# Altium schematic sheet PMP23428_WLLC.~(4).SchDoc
size 431 x 279 mm; Date: Not shown in title block; ApprovedBy: Not shown in title block; CheckedBy: Not shown in title block; Author: Not shown in title block; CompanyName: Not shown in title block; Engineer: Not shown in title block; Organization: Not shown in title block; Address1: Not shown in title block; Address2: Not shown in title block; Address3: Not shown in title block; Address4: Not shown in title block; DocumentNumber: 1; Revision: Use project parameter SCH_Rev; SheetNumber: 3; SheetTotal: 4; PageSetup: Record=PageOptions¦CenterHorizontal=True¦CenterVertical=True¦PrintScale=1.00¦XCorrection=1.00¦YCorrection=1.00¦PrintKind=0¦BorderSize=5000000¦LeftOffset=0¦BottomOffset=0¦Orientation=2¦PaperLength=1000¦PaperWidth=1000¦Scale=100¦PaperSource=15¦PrintQuality=600¦MediaType=1¦DitherType=10¦PaperKind=Letter¦PrintScaleMode=1
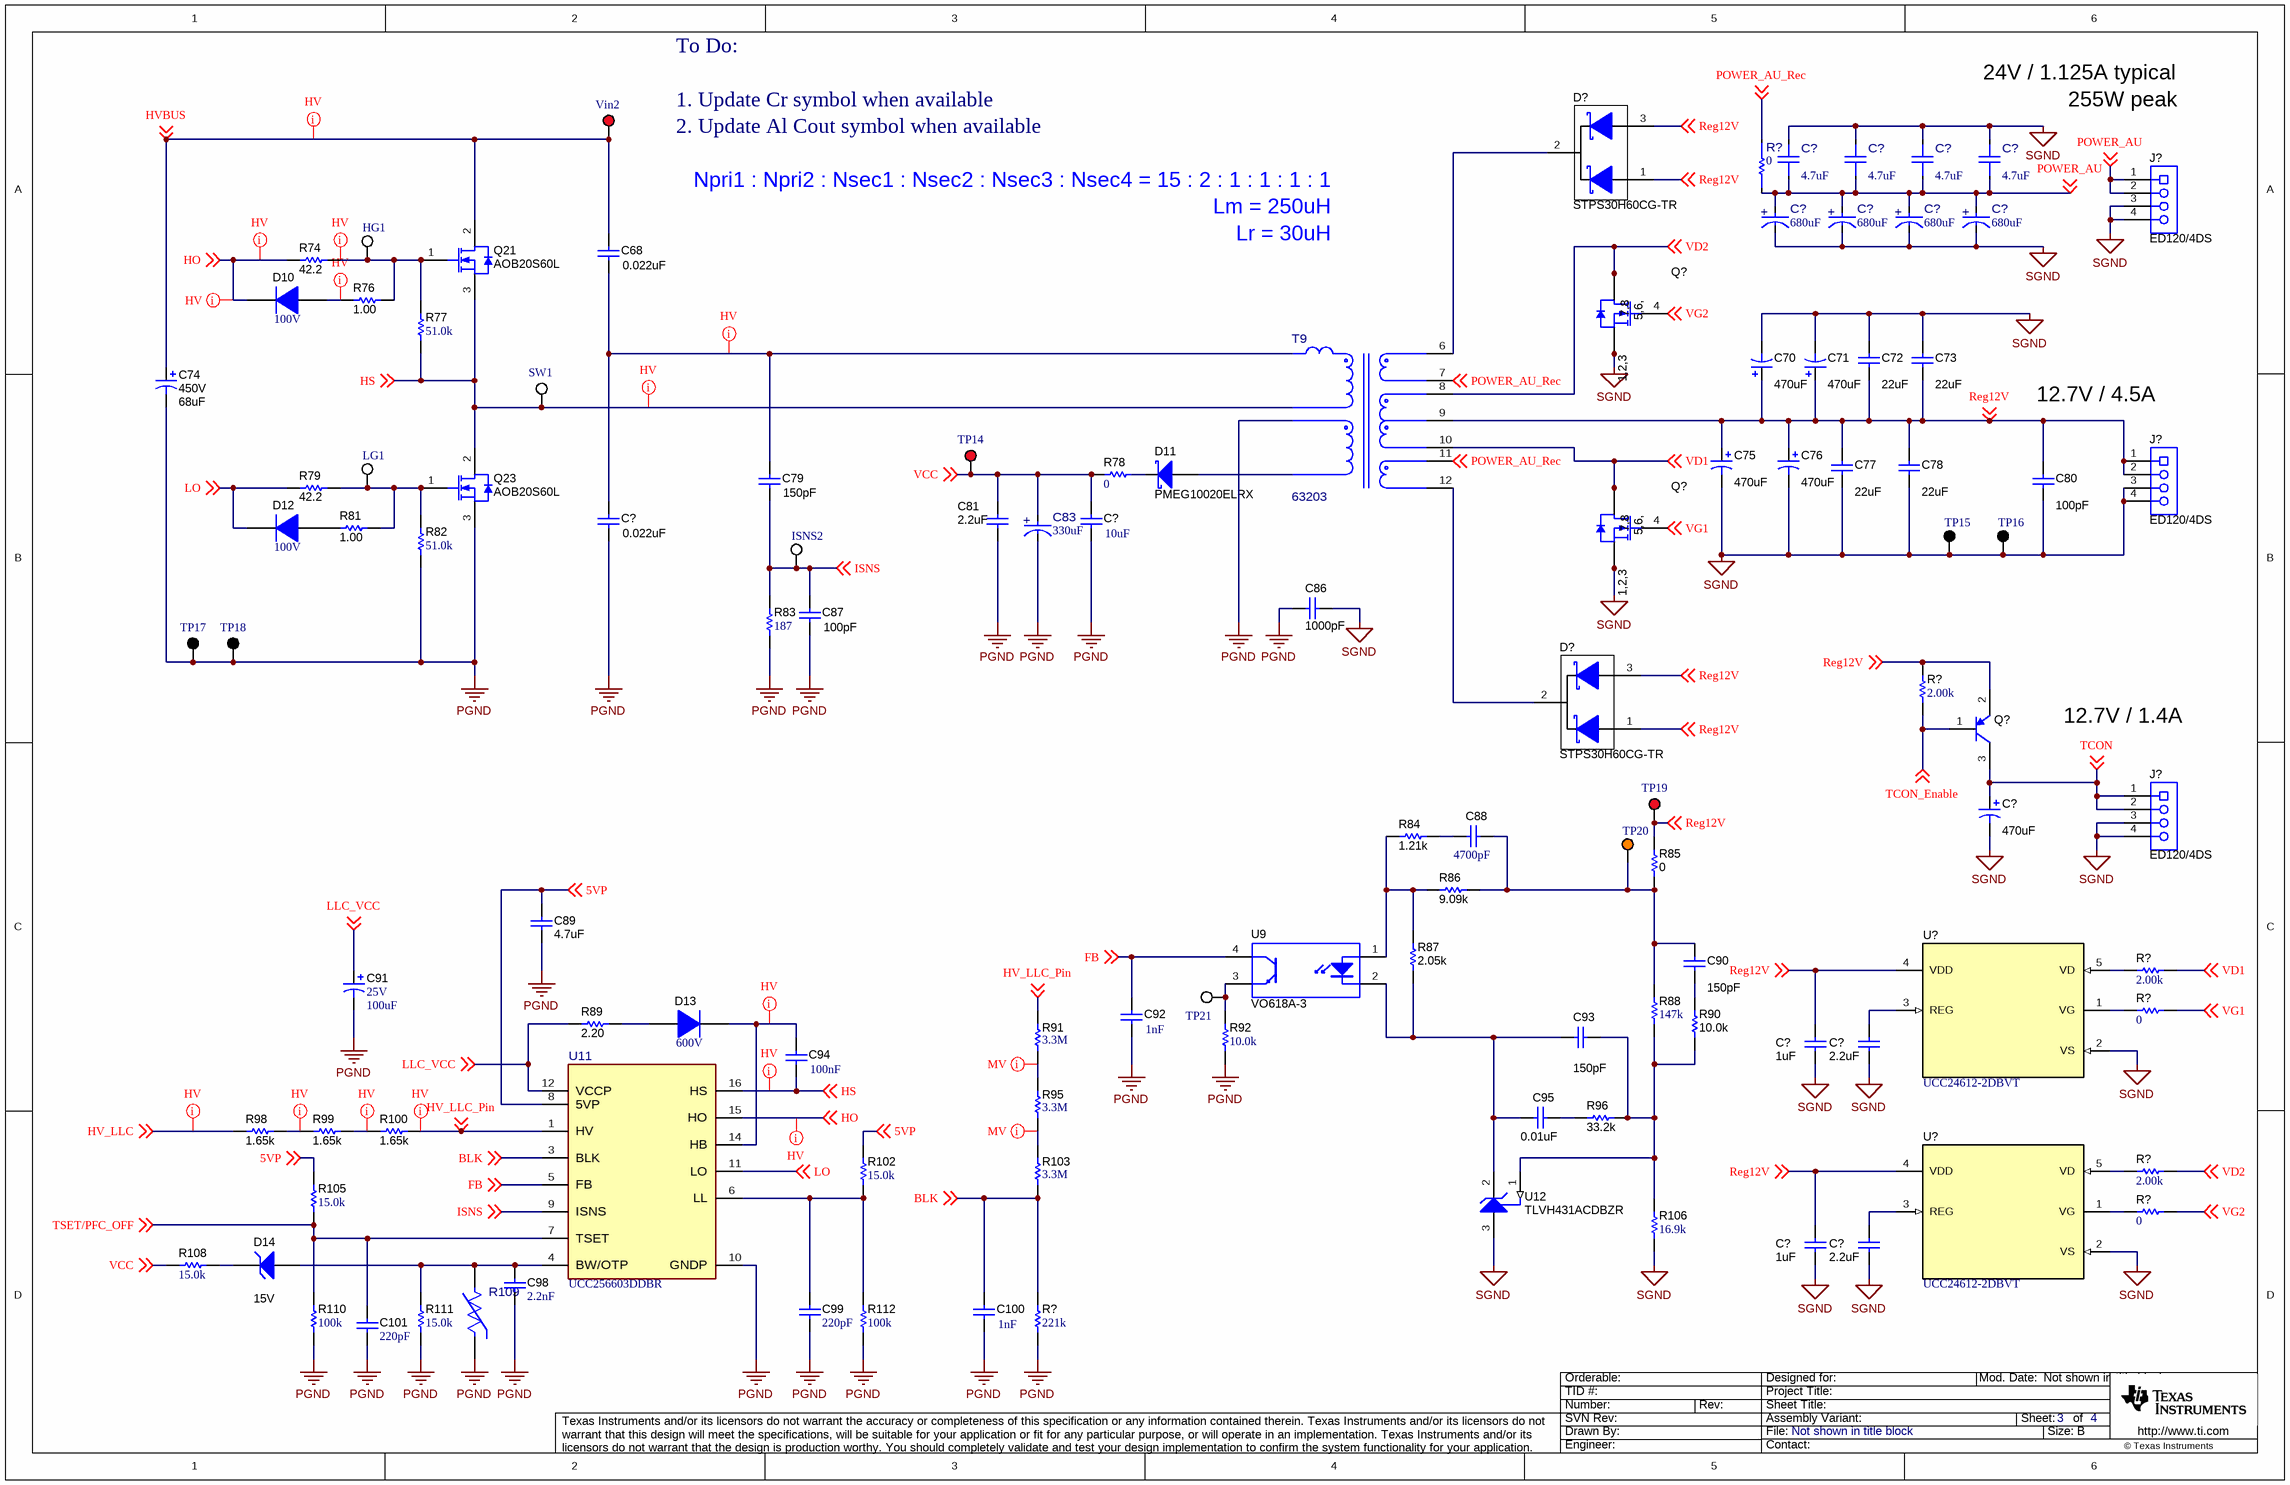
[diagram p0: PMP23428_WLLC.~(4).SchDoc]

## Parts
(Parts that share a designator on the sheet are numbered #1, #2 ... from top to bottom, then left to right.)
C68  ValueDisplayed: 0.022uF  [B32652_1800x700x1250]  (hidden comment: B32652A7153J000)
C70  ValueDisplayed: 470uF  [HW_1000x1600]  (hidden comment: UHW1V471MPD)
C71  ValueDisplayed: 470uF  [HW_1000x1600]  (hidden comment: UHW1V471MPD)
C72  ValueDisplayed: 22uF  [1206_190L]  (hidden comment: C3216X5R1E226M160AB)
C73  ValueDisplayed: 22uF  [1206_190L]  (hidden comment: C3216X5R1E226M160AB)
C74  VDC_V: 450V  ValueDisplayed: 68uF  [KXG_1800x3150]  (hidden comment: EKXG451ELL680MMN3S)
C75  ValueDisplayed: 470uF  [HW_1000x1600]  (hidden comment: UHW1V471MPD)
C76  ValueDisplayed: 470uF  [HW_1000x1600]  (hidden comment: UHW1V471MPD)
C77  ValueDisplayed: 22uF  [1206_190L]  (hidden comment: C3216X5R1E226M160AB)
C78  ValueDisplayed: 22uF  [1206_190L]  (hidden comment: C3216X5R1E226M160AB)
C79  ValueDisplayed: 150pF  [1206L]  (hidden comment: GRM31A5C2J151JW01D)
C80  ValueDisplayed: 100pF  [0603L]  (hidden comment: 06035A101FAT2A)
C81  ValueDisplayed: 2.2uF  [0805L]  (hidden comment: C2012X7R1V225K085AC)
C83  ValueDisplayed: 330uF  [FP-35ZL330MEFC10X16_RADIAL-MFG]  (hidden comment: 35ZL330MEFC10X16)
C86  ValueDisplayed: 1000pF  [CD45_700x600x1100]  (hidden comment: CD45-E2GA102M-NKA)
C87  ValueDisplayed: 100pF  [1206L]  (hidden comment: 12061A101JAT2A)
C88  ValueDisplayed: 4700pF  [0603L]  (hidden comment: C0603C472J1GAC7867)
C89  ValueDisplayed: 4.7uF  [1206L]  (hidden comment: C3216X7R1E475K085AB)
C90  ValueDisplayed: 150pF  [0402L]  (hidden comment: 885012005062)
C91  VDC_V: 25V  ValueDisplayed: 100uF  [SM_RADIAL_E]  (hidden comment: EEE-FK1E101P)
C92  Cap_F: 1nF  [1206L]  (hidden comment: 12061A102JAT2A)
C93  ValueDisplayed: 150pF  [0402L]  (hidden comment: 885012005062)
C94  Cap_F: 100nF  [1206_180L]  (hidden comment: GRM31C5C1E104JA01L)
C95  ValueDisplayed: 0.01uF  [0603L]  (hidden comment: 06031C103JAT2A)
C98  Cap_F: 2.2nF  [0603]  (hidden comment: C0603X222K5RACTU)
C99  Cap_F: 220pF  [0603]  (hidden comment: C0603X221K5RACTU)
C100  Cap_F: 1nF  [0402L]  (hidden comment: 04025C102JAT2A)
C101  Cap_F: 220pF  [0603]  (hidden comment: C0603X221K5RACTU)
C?#1  ValueDisplayed: 4.7uF  [FP-885012208094_1206-MFG]  (hidden comment: 885012208094)
C?#2  ValueDisplayed: 4.7uF  [FP-885012208094_1206-MFG]  (hidden comment: 885012208094)
C?#3  ValueDisplayed: 4.7uF  [FP-885012208094_1206-MFG]  (hidden comment: 885012208094)
C?#4  ValueDisplayed: 4.7uF  [FP-885012208094_1206-MFG]  (hidden comment: 885012208094)
C?#5  ValueDisplayed: 680uF  [FP-EKZM350ELL681MJ25S_RADIAL-MFG]  (hidden comment: EKZM350ELL681MJ25S)
C?#6  ValueDisplayed: 680uF  [FP-EKZM350ELL681MJ25S_RADIAL-MFG]  (hidden comment: EKZM350ELL681MJ25S)
C?#7  ValueDisplayed: 680uF  [FP-EKZM350ELL681MJ25S_RADIAL-MFG]  (hidden comment: EKZM350ELL681MJ25S)
C?#8  ValueDisplayed: 680uF  [FP-EKZM350ELL681MJ25S_RADIAL-MFG]  (hidden comment: EKZM350ELL681MJ25S)
C?#9  ValueDisplayed: 0.022uF  [B32652_1800x700x1250]  (hidden comment: B32652A7153J000)
C?#10  ValueDisplayed: 10uF  [1210_270]  (hidden comment: GRM32ER6YA106KA12L)
C?#11  ValueDisplayed: 470uF  [HW_1000x1600]  (hidden comment: UHW1V471MPD)
C?#12  ValueDisplayed: 1uF  [0603L]  (hidden comment: GRM188R71C105KE15D)
C?#13  ValueDisplayed: 2.2uF  [0805L]  (hidden comment: C2012X7R1V225K085AC)
C?#14  ValueDisplayed: 1uF  [0603L]  (hidden comment: GRM188R71C105KE15D)
C?#15  ValueDisplayed: 2.2uF  [0805L]  (hidden comment: C2012X7R1V225K085AC)
D10  Vr_V: 100V  [SOD-123]  (hidden comment: 1N4148W-7-F)
D11  PMEG10020ELRX  [SOD-123W]
D12  Vr_V: 100V  [SOD-123]  (hidden comment: 1N4148W-7-F)
D13  Vr_V: 600V  [SMAF]  (hidden comment: ES1JAF)
D14  value 15V  [SOD-123]  (hidden comment: DDZ15-7)
D?#1  STPS30H60CG-TR  [DDPAK]
D?#2  STPS30H60CG-TR  [DDPAK]
HG1  5012  [Keystone5012]  (value not drawn)
ISNS2  5012  [Keystone5012]  (value not drawn)
J?#1  ED120/4DS  [On-Shore_ED120_4DS]
J?#2  ED120/4DS  [On-Shore_ED120_4DS]
J?#3  ED120/4DS  [On-Shore_ED120_4DS]
LG1  5012  [Keystone5012]  (value not drawn)
Q21  AOB20S60L  [DDPAK]
Q23  AOB20S60L  [DDPAK]
Q?#1  CSD19502Q5B  [DNK0008A]  (value not drawn)
Q?#2  CSD19502Q5B  [DNK0008A]  (value not drawn)
Q?#3  ZXTP25040DFHTA  [SOT-23]  (value not drawn)
R74  ValueDisplayed: 42.2  [0603]  (hidden comment: RC0603FR-0742R2L)
R76  ValueDisplayed: 1.00  [0603L]  (hidden comment: RC0603FR-071RL)
R77  ValueDisplayed: 51.0k  [0603L]  (hidden comment: RC0603FR-0751KL)
R78  ValueDisplayed: 0  [1206L]  (hidden comment: ERJ-8GEY0R00V)
R79  ValueDisplayed: 42.2  [0603L]  (hidden comment: RC0603FR-0742R2L)
R81  ValueDisplayed: 1.00  [0603L]  (hidden comment: RC0603FR-071RL)
R82  ValueDisplayed: 51.0k  [0603L]  (hidden comment: RC0603FR-0751KL)
R83  ValueDisplayed: 187  [1206]  (hidden comment: RC1206FR-07187RL)
R84  ValueDisplayed: 1.21k  [0603L]  (hidden comment: RC0603FR-071K21L)
R85  ValueDisplayed: 0  [0402L]  (hidden comment: RC0402JR-070RL)
R86  ValueDisplayed: 9.09k  [0603L]  (hidden comment: RC0603FR-079K09L)
R87  ValueDisplayed: 2.05k  [0603L]  (hidden comment: RC0603FR-072K05L)
R88  ValueDisplayed: 147k  [0603L]  (hidden comment: RC0603FR-07147KL)
R89  ValueDisplayed: 2.20  [0603L]  (hidden comment: ERJ-3RQF2R2V)
R90  ValueDisplayed: 10.0k  [0603L]  (hidden comment: ERJ-3EKF1002V)
R91  Res_ohm: 3.3M  [FP-KTR18EZPF3304_1206-MFG]  (hidden comment: KTR18EZPF3304)
R92  ValueDisplayed: 10.0k  [0402L]  (hidden comment: ERJ-2RKF1002X)
R95  Res_ohm: 3.3M  [FP-KTR18EZPF3304_1206-MFG]  (hidden comment: KTR18EZPF3304)
R96  ValueDisplayed: 33.2k  [0603L]  (hidden comment: RC0603FR-0733K2L)
R98  ValueDisplayed: 1.65k  [1206L]  (hidden comment: CRCW12061K65FKEA)
R99  ValueDisplayed: 1.65k  [1206L]  (hidden comment: CRCW12061K65FKEA)
R100  ValueDisplayed: 1.65k  [1206L]  (hidden comment: CRCW12061K65FKEA)
R102  ValueDisplayed: 15.0k  [0603]  (hidden comment: RT0603BRD0715KL)
R103  Res_ohm: 3.3M  [FP-KTR18EZPF3304_1206-MFG]  (hidden comment: KTR18EZPF3304)
R105  ValueDisplayed: 15.0k  [0603]  (hidden comment: RT0603BRD0715KL)
R106  ValueDisplayed: 16.9k  [0603L]  (hidden comment: RC0603FR-0716K9L)
R108  ValueDisplayed: 15.0k  [0603]  (hidden comment: RG1608P-153-B-T5)
R109  B57371V2474J060  [FP-B57371V2474J060_0603-MFG]  (value not drawn)
R110  ValueDisplayed: 100k  [0603]  (hidden comment: RT0603BRD07100KL)
R111  ValueDisplayed: 15.0k  [0603]  (hidden comment: RG1608P-153-B-T5)
R112  ValueDisplayed: 100k  [0603]  (hidden comment: RT0603BRD07100KL)
R?#1  value 0  [FP-RMCF1206ZT0R00_1206-MFG]  (hidden comment: RMCF1206ZT0R00)
R?#2  ValueDisplayed: 2.00k  [0603]  (hidden comment: RC0603FR-072KL)
R?#3  ValueDisplayed: 2.00k  [0603]  (hidden comment: RC0603FR-072KL)
R?#4  ValueDisplayed: 0  [0603L]  (hidden comment: RC0603JR-070RL)
R?#5  ValueDisplayed: 2.00k  [0603]  (hidden comment: RC0603FR-072KL)
R?#6  ValueDisplayed: 0  [0603L]  (hidden comment: RC0603JR-070RL)
R?#7  ValueDisplayed: 221k  [0603]  (hidden comment: RC0603FR-07221KL)
SW1  5012  [Keystone5012]  (value not drawn)
T9  63203  [FP-63203_W80MM0_H64MM0-MFG]
TP14  5010  [Keystone5010]  (value not drawn)
TP15  5011  [Keystone5011]  (value not drawn)
TP16  5011  [Keystone5011]  (value not drawn)
TP17  5011  [Keystone5011]  (value not drawn)
TP18  5011  [Keystone5011]  (value not drawn)
TP19  5010  [Keystone5010]  (value not drawn)
TP20  5013  [Keystone5013]  (value not drawn)
TP21  5012  [Keystone5012]  (value not drawn)
U9  VO618A-3  [DIP-4]
U11  UCC256603DDBR  [DDB0014A-MFG]
U12  TLVH431ACDBZR  [DBZ0003A_N]
U?#1  UCC24612-2DBVT  [DBV0005A_N]
U?#2  UCC24612-2DBVT  [DBV0005A_N]
Vin2  5010  [Keystone5010]  (value not drawn)

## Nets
PGND: C74.2(-) C81.2 C83.1(CATHODE) C86.2 C87.2 C89.2 C91.2(-) C92.2 C98.2 C99.2 C100.2 C101.2 C?#9.2 C?#10.2 Q23.3(S) R82.1 R83.1 R92.1 R109.1 R110.1 R111.1 R112.1 R?#7.1 TP17.1 TP18.1 U11.10(GNDP)
SGND: C70.2(-) C71.2(-) C72.1 C73.1 C75.2(-) C76.2(-) C77.2 C78.2 C80.2 C86.1 C?#1.2 C?#2.2 C?#3.2 C?#4.2 C?#5.1(CATHODE) C?#6.1(CATHODE) C?#7.1(CATHODE) C?#8.1(CATHODE) C?#11.2(-) C?#12.2 C?#13.2 C?#14.2 C?#15.2 J?#1.3 J?#1.4 J?#2.3 J?#2.4 J?#3.3 J?#3.4 Q?#1.1(S) Q?#1.2(S) Q?#1.3(S) Q?#2.1(S) Q?#2.2(S) Q?#2.3(S) R106.1 TP15.1 TP16.1 U12.3(ANODE) U?#1.2(VS) U?#2.2(VS)
5VP: C89.1 R102.2 R105.2 U11.8(5VP) ; off-sheet 5VP
BLK: C100.1 R103.1 R?#7.2 U11.3(BLK) ; off-sheet BLK
FB: C92.1 U9.4(C) U11.5(FB) ; off-sheet FB
HO: D10.1(K) R74.1 U11.15(HO) ; off-sheet HO
HS: C94.2 Q21.3(S) Q23.2(D) R77.1 SW1.1 U11.16(HS) ; off-sheet HS
HV_LLC: R98.1 ; off-sheet HV_LLC
HV_LLC_Pin: R91.2 R100.2 U11.1(HV) ; off-sheet HV_LLC_Pin
HVBUS: C68.1 C74.1(+) Q21.2(D) Vin2.1 ; off-sheet HVBUS
ISNS: C79.2 C87.1 ISNS2.1 R83.2 U11.9(ISNS) ; off-sheet ISNS
LLC_VCC: C91.1(+) R89.1 U11.12(VCCP) ; off-sheet LLC_VCC
LO: D12.1(K) R79.1 U11.11(LO) ; off-sheet LO
POWER_AU: C?#1.1 C?#2.1 C?#3.1 C?#4.1 C?#5.2(ANODE) C?#6.2(ANODE) C?#7.2(ANODE) C?#8.2(ANODE) J?#1.1 J?#1.2 R?#1.2 ; off-sheet POWER_AU
POWER_AU_Rec: R?#1.1 T9.7 T9.11 ; off-sheet POWER_AU_Rec
Reg12V: C70.1(+) C71.1(+) C72.2 C73.2 C75.1(+) C76.1(+) C77.1 C78.1 C80.1 C?#12.1 C?#14.1 D?#1.1(A) D?#1.3(A) D?#2.1(A) D?#2.3(A) J?#2.1 J?#2.2 Q?#3.2(E) R85.2 R?#2.2 T9.9 TP19.1 U?#1.4(VDD) U?#2.4(VDD) ; off-sheet Reg12V
TCON: C?#11.1(+) J?#3.1 J?#3.2 Q?#3.3(C) ; off-sheet TCON
TCON_Enable: Q?#3.1(B) R?#2.1 ; off-sheet TCON_Enable
TSET/PFC_OFF: C101.1 R105.1 R110.2 U11.7(TSET) ; off-sheet TSET/PFC_OFF
VCC: C81.1 C83.2(ANODE) C?#10.1 R78.1 R108.2 TP14.1 ; off-sheet VCC
VD1: Q?#2.5(D) Q?#2.6(D) Q?#2.7(D) Q?#2.8(D) Q?#2.9(D) R?#3.2 T9.10 ; off-sheet VD1
VD2: Q?#1.5(D) Q?#1.6(D) Q?#1.7(D) Q?#1.8(D) Q?#1.9(D) R?#5.2 T9.8 ; off-sheet VD2
VG1: Q?#2.4(G) R?#4.1 ; off-sheet VG1
VG2: Q?#1.4(G) R?#6.1 ; off-sheet VG2
NetC68_2: C68.2 C79.1 C?#9.1
NetC88_1: C88.1 C90.1 R85.1 R86.2 R88.2 TP20.1
NetC88_2: C88.2 R84.2
NetC90_2: C90.2 R90.2
NetC93_1: C93.1 R88.1 R90.1 R96.1 R106.2 U12.1(REF)
NetC93_2: C93.2 C95.2 R87.1 U9.2(K) U12.2(CATHODE)
NetC94_1: C94.1 D13.1(K) U11.14(HB)
NetC95_1: C95.1 R96.2
NetC98_1: C98.1 D14.2(A) R109.2 R111.2 U11.4(BW/OTP)
NetC99_1: C99.1 R102.1 R112.2 U11.6(LL)
NetC?#13_1: C?#13.1 U?#1.3(REG)
NetC?#15_1: C?#15.1 U?#2.3(REG)
NetD10_2: D10.2(A) R76.1
NetD11_1: D11.1(K) R78.2
NetD12_2: D12.2(A) R81.1
NetD13_2: D13.2(A) R89.2
NetD14_1: D14.1(K) R108.1
NetD?#1_2: D?#1.2(K) T9.6
NetD?#2_2: D?#2.2(K) T9.12
NetHG1_1: HG1.1 Q21.1(G) R74.2 R76.2 R77.2
NetLG1_1: LG1.1 Q23.1(G) R79.2 R81.2 R82.2
NetR84_1: R84.1 R86.1 R87.2 U9.1(A)
NetR91_1: R91.1 R95.2
NetR92_2: R92.2 TP21.1 U9.3(E)
NetR95_1: R95.1 R103.2
NetR98_2: R98.2 R99.1
NetR99_2: R99.2 R100.1
NetR?#3_1: R?#3.1 U?#1.5(VD)
NetR?#4_2: R?#4.2 U?#1.1(VG)
NetR?#5_1: R?#5.1 U?#2.5(VD)
NetR?#6_2: R?#6.2 U?#2.1(VG)

Not connected (* = marked no-connect by the designer): D11 2(A)

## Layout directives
net class HV: HO, HS, HV_LLC, HV_LLC_Pin, HVBUS, NetC68_2, NetC94_1, NetD10_2, NetHG1_1, NetR98_2, NetR99_2
net class MV: NetR91_1, NetR95_1

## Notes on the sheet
- To Do:
- 255W peak
- 24V / 1.125A typical
- 1. Update Cr symbol when available
- 2. Update Al Cout symbol when available
- Lm = 250uH
- Lr = 30uH
- Npri1 : Npri2 : Nsec1 : Nsec2 : Nsec3 : Nsec4 = 15 : 2 : 1 : 1 : 1 : 1
- 12.7V / 4.5A
- 12.7V / 1.4A

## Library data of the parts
C68 C?#9 = CMP-0012346-3: Manufacturer: TDK; TaMin_C: -55°C; Polarized: N; SizeAreaWB_mm2: 180; Value1: Unknown; Value: 0.015uF; TaMax_C: 100°C; Tolerance_%: 5%; SizeZ_mm: 12.5; SizeX_mm: 18; SizeY_mm: 7; Cap_Case: 18x7x12.5; Value2: 1250V; SizeArea_mm2: 126; CompType: Capacitor; AEC Qualified: Y; Cap_F: 15nF; VDC_V: 1.25kV; AEC Grade: 3; AEC Category: Q200
C70 C71 C75 C76 C?#11 = CMP-0010541-2: CAP, AL, 470 uF, 35 V, +/- 20%, 0.03 ohm, TH; Manufacturer: Nichicon; TaMin_C: -40°C; ESR_ohm: 0.03; Polarized: Y; SizeAreaWB_mm2: 144; U/M: EA; Value: 470uF; TaMax_C: 105°C; SizeZ_mm: 17.5; SizeX_mm: 10; Cap_Case: 10x16mm; Value2: 35V; SizeArea_mm2: 100; CompType: Capacitor; AEC Qualified: N; Cap_F: 470µF; IRMS_A: 2A; AEC Category: Q200
C72 C73 C77 C78 = CMP-0008654-2: CAP, CERM, 22 uF, 25 V, +/- 20%, X5R, 1206_190; Manufacturer: TDK; TaMin_C: -55°C; Polarized: N; SizeAreaWB_mm2: 10.92; Value1: Unknown; U/M: EA; Value: 22uF; TaMax_C: 85°C; SizeZ_mm: 1.9; SizeX_mm: 3.2; SizeY_mm: 1.6; Cap_Case: 1206; Value2: 25V; SizeArea_mm2: 5.12; CompType: Capacitor; Cap_F: 22µF; AEC Category: Q200
C74 = CMP-0010043-2: CAP, AL, 68 uF, 450 V, +/- 20%, TH; Manufacturer: Chemi-Con; TaMin_C: -25°C; Polarized: Y; SizeAreaWB_mm2: 400; Value1: Unknown; U/M: EA; Value: 68uF; TaMax_C: 105°C; SizeZ_mm: 33; SizeX_mm: 18; Cap_Case: 18x31.5mm; SizeArea_mm2: 324; CompType: Capacitor; Cap_F: 68µF; IRMS_A: 6.3dA; AEC Category: Q200
C79 = CMP-0008885-2: CAP, CERM, 150 pF, 630 V, +/- 5%, C0G/NP0, 1206; Manufacturer: MuRata; TaMin_C: -55°C; Polarized: N; SizeAreaWB_mm2: 10.92; Value1: Unknown; U/M: EA; Value: 150pF; TaMax_C: 125°C; SizeZ_mm: 1.35; SizeX_mm: 3.2; SizeY_mm: 1.6; Cap_Case: 1206; Value2: 630V; SizeArea_mm2: 5.12; CompType: Capacitor; AEC Category: Q200
C80 = CMP-0006762-4: CAP, CERM, 100 pF, 50 V, +/- 1%, C0G/NP0, 0603; Manufacturer: AVX; TaMin_C: -55°C; Polarized: N; SizeAreaWB_mm2: 4.68; Value1: Unknown; U/M: EA; TaMax_C: 125°C; SizeZ_mm: 1; SizeX_mm: 1.6; SizeY_mm: 0.8; Cap_Case: 0603; Value2: 50V; SizeArea_mm2: 1.28; CompType: Capacitor; Value: 100pF; AEC Category: Q200
C81 C?#13 C?#15 = CMP-0007883-2: CAP, CERM, 2.2 uF, 35 V, +/- 10%, X7R, 0805; Manufacturer: TDK; TaMin_C: -55°C; Polarized: N; SizeAreaWB_mm2: 6.75; Value1: Unknown; U/M: EA; Value: 2.2uF; TaMax_C: 125°C; SizeZ_mm: 1.45; SizeX_mm: 2; SizeY_mm: 1.25; Cap_Case: 0805; Value2: 35V; SizeArea_mm2: 2.5; CompType: Capacitor; Cap_F: 2.2µF; AEC Category: Q200
C83 = CMP-0098283-1: Cap Aluminum Lytic 330uF 35V 20% (10 X 16mm) Radial 5mm 1430mA 4000h 105C Bulk; Manufacturer: Rubycon; AEC Qualified: No; Cap_F: 330µF; IRMS_A: 1.43A; SizeZ_mm: 17.5mm; Dissipation Factor: 12%; Leakage Current: 115.5uA; Life: 4000Hours; Value: 330µF
C86 = CMP-0009595-2: CAP, CERM, 1000 pF,  V, +/- 20%, E, D7xT6mm; Manufacturer: TDK; TaMin_C: -25°C; Polarized: N; SizeAreaWB_mm2: 101.2; Value1: Unknown; U/M: EA; Value: 1000pF; TaMax_C: 125°C; SizeZ_mm: 11; SizeX_mm: 10.65; SizeY_mm: 6; Cap_Case: 7x6x11mm; SizeArea_mm2: 63.9; Cap_F: 1nF; AEC Category: Q200
C87 = CMP-0008462-2: CAP, CERM, 100 pF, 100 V, +/- 5%, C0G/NP0, 1206; Manufacturer: AVX; TaMin_C: -55°C; ESR_ohm: 7.01d; Polarized: N; SizeAreaWB_mm2: 10.92; Value1: 0.701 ohm; U/M: EA; Value: 100pF; TaMax_C: 125°C; SizeZ_mm: 1.35; SizeX_mm: 3.2; SizeY_mm: 1.6; Cap_Case: 1206; Value2: 100V; SizeArea_mm2: 5.12; CompType: Capacitor; AEC Category: Q200
C88 = CMP-0006941-4: CAP, CERM, 4700 pF, 100 V, +/- 5%, C0G/NP0, 0603; Manufacturer: Kemet; TaMin_C: -55°C; Polarized: N; SizeAreaWB_mm2: 4.68; Value1: Unknown; U/M: EA; Value: 4700pF; TaMax_C: 125°C; SizeZ_mm: 1; SizeX_mm: 1.6; SizeY_mm: 0.8; Cap_Case: 0603; Value2: 100V; SizeArea_mm2: 1.28; Cap_F: 4.7nF; AEC Category: Q200
C89 = CMP-0008693-2: CAP, CERM, 4.7 uF, 25 V, +/- 10%, X7R, 1206; Manufacturer: TDK; TaMin_C: -55°C; Polarized: N; SizeAreaWB_mm2: 10.92; Value1: Unknown; U/M: EA; Value: 4.7uF; TaMax_C: 125°C; SizeZ_mm: 1.35; SizeX_mm: 3.2; SizeY_mm: 1.6; Cap_Case: 1206; Value2: 25V; SizeArea_mm2: 5.12; CompType: Capacitor; Cap_F: 4.7µF; AEC Category: Q200
C90 C93 = CMP-0064913-2: CAP, CERM, 150 pF, 50 V,+/- 5%, C0G/NP0, 0402; Manufacturer: Wurth Elektronik; TaMin_C: -55°C; Polarized: N; SizeAreaWB_mm2: 3; Value1: Unknown; U/M: EA; Value: 150pF; TaMax_C: 125°C; SizeZ_mm: 0.6; SizeX_mm: 1; SizeY_mm: 0.5; Cap_Case: 0402; Value2: 50V; CompType: Capacitor; AEC Category: Q200
C91 = CMP-0010710-1: CAP, AL, 100 uF, 25 V, +/- 20%, 0.26 ohm, AEC-Q200 Grade 2, SMD; Manufacturer: Panasonic; TaMin_C: -55°C; ESR_ohm: 2.6d; Polarized: Y; SizeAreaWB_mm2: 118.45; U/M: EA; Value: 100uF; TaMax_C: 105°C; SizeZ_mm: 6.2; SizeX_mm: 9.5; SizeY_mm: 8.3; Cap_Case: E; SizeArea_mm2: 78.85; CompType: Capacitor; Cap_F: 100µF; IRMS_A: 3dA; AEC Grade: 2; AEC Category: Q200
C92 = CMP-0008465-2: CAP, CERM, 1000 pF, 100 V, +/- 5%, C0G/NP0, 1206; Manufacturer: AVX; TaMin_C: -55°C; ESR_ohm: 2.38d; Polarized: N; SizeAreaWB_mm2: 10.92; Value1: 0.238 ohm; U/M: EA; Value: 1000pF; TaMax_C: 125°C; SizeZ_mm: 1.35; SizeX_mm: 3.2; SizeY_mm: 1.6; Cap_Case: 1206; Value2: 100V; SizeArea_mm2: 5.12; AEC Category: Q200
C94 = CMP-0064950-2: CAP, CERM, 0.1 uF, 25 V,+/- 5%, C0G/NP0, 1206; Manufacturer: MuRata; TaMin_C: -55°C; Polarized: N; SizeAreaWB_mm2: 10.92; Value1: Unknown; U/M: EA; Value: 0.1uF; TaMax_C: 125°C; SizeZ_mm: 1.8; SizeX_mm: 3.2; SizeY_mm: 1.6; Cap_Case: 1206; Value2: 25V; SizeArea_mm2: 5.12; AEC Category: Q200
C95 = CMP-0006726-4: CAP, CERM, 0.01 uF, 100 V, +/- 5%, X7R, 0603; Manufacturer: AVX; TaMin_C: -55°C; ESR_ohm: 0.098; Polarized: N; SizeAreaWB_mm2: 4.68; Value1: 0.098 ohm; U/M: EA; Value: 0.01uF; TaMax_C: 125°C; SizeZ_mm: 1; SizeX_mm: 1.6; SizeY_mm: 0.8; Cap_Case: 0603; Value2: 100V; SizeArea_mm2: 1.28; Cap_F: 10nF; AEC Category: Q200
C98 = CMP-0006983-4: CAP, CERM, 2200 pF, 50 V, +/- 10%, X7R, 0603; Manufacturer: Kemet; TaMin_C: -55°C; Polarized: N; SizeAreaWB_mm2: 4.68; Value1: Unknown; U/M: EA; Value: 2200pF; TaMax_C: 125°C; SizeZ_mm: 1; SizeX_mm: 1.6; SizeY_mm: 0.8; Value2: 50V; SizeArea_mm2: 1.28; AEC Category: Q200
C99 C101 = CMP-0006982-4: CAP, CERM, 220 pF, 50 V, +/- 10%, X7R, 0603; Manufacturer: Kemet; TaMin_C: -55°C; Polarized: N; SizeAreaWB_mm2: 4.68; Value1: Unknown; U/M: EA; Value: 220pF; TaMax_C: 125°C; SizeZ_mm: 1; SizeX_mm: 1.6; SizeY_mm: 0.8; Value2: 50V; SizeArea_mm2: 1.28; AEC Category: Q200
C100 = CMP-0861060-1: CAP, CERM, 1000 pF, 50 V,+/- 5%, X7R, 0402; Manufacturer: AVX; Value2: 50V; SizeY_mm: 0.5; AEC Category: Q200; Polarized: N; Green_Lifecycle: Active; SizeAreaWB_mm2: 3; ValueDisplayed: 1000pF; Cap_Case: 0402; Value: 1000pF; TaMin_C: -55°C; U/M: EA; Green_REACh: Passed; SizeZ_mm: 0.6; SizeX_mm: 1; TaMax_C: 125°C
C?#1-C?#4 = CMP-0088282-2: 4.7µF ±10% 50V Ceramic Capacitor X7R 1206 (3216 Metric); Manufacturer: Wurth Electronics; TempCo: 15%; Symbol Name: SYM-885012208094; SizeZ_mm: 1.9mm; AEC Qualified: No
C?#5-C?#8 = CMP-0001423-1: Cap Aluminum Lytic 680uF 35V 20% (10 X 25mm) Radial 5mm 2250mA 10000h 105 Bulk; Manufacturer: United Chemi-Con; AEC Qualified: No; Cap_F: 680µF; IRMS_A: 2.25A; SizeZ_mm: 26.5mm; Dissipation Factor: 12%; Leakage Current: 238uA; Life: 10000Hours; Value: 680µF
C?#10 = CMP-0009215-2: CAP, CERM, 10 uF, 35 V, +/- 10%, X5R, 1210; Manufacturer: MuRata; TaMin_C: -55°C; Polarized: N; SizeAreaWB_mm2: 14.7; Value1: Unknown; U/M: EA; Value: 10uF; TaMax_C: 85°C; SizeZ_mm: 2.7; SizeX_mm: 3.2; SizeY_mm: 2.5; Cap_Case: 1210; Value2: 35V; SizeArea_mm2: 8; Cap_F: 10µF; AEC Category: Q200
C?#12 C?#14 = CMP-0007380-4: CAP, CERM, 1 uF, 16 V, +/- 10%, X7R, 0603; Manufacturer: MuRata; TaMin_C: -55°C; Polarized: N; SizeAreaWB_mm2: 4.68; Value1: Unknown; U/M: EA; Value: 1uF; TaMax_C: 125°C; SizeZ_mm: 1; SizeX_mm: 1.6; SizeY_mm: 0.8; Cap_Case: 0603; Value2: 16V; SizeArea_mm2: 1.28; CompType: Capacitor; Cap_F: 1µF; AEC Category: Q200
D10 D12 = CMP-0029001-2: Diode, Ultrafast, 100 V, 0.15 A, SOD-123; Manufacturer: Diodes Inc.; Io_A: 150mA; Green_Lifecycle: Active; SizeAreaWB_mm2: 13.095; Green_REACh: Passed; Value1: 0.15A; TJmax_C: 150°C; Value: 100V; SizeZ_mm: 1.35; SizeX_mm: 3.85; SizeY_mm: 1.7; Vf_V: 1.25V; SizeArea_mm2: 6.545; AEC Category: Q101
D11 = CMP-0028977-2: Diode, Schottky, 100 V, 2 A, AEC-Q101, SOD-123W; Manufacturer: Nexperia; Io_A: 2A; SizeAreaWB_mm2: 12.15; Vr_V: 100V; TJmax_C: 175°C; Value: 100V; SizeZ_mm: 1; SizeX_mm: 3.5; SizeY_mm: 1.7; Vf_V: 830mV; Value2: 0.83V; SizeArea_mm2: 5.95; AEC Qualified: Y; AEC Category: Q101
D13 = CMP-0029162-2: Diode, Ultrafast, 600 V, 1 A, AEC-Q101, SMAF; Manufacturer: Fairchild Semiconductor; Io_A: 1A; Green_Lifecycle: Not Set; SizeAreaWB_mm2: 19.95; Green_REACh: Incomplete; TJmax_C: 150°C; Value: 600V; SizeZ_mm: 1; SizeX_mm: 4.7; SizeY_mm: 2.5; Vf_V: 1.7V; SizeArea_mm2: 11.75; AEC Qualified: Y; AEC Category: Q101
D14 = CMP-0085135-1: Diode, Zener, 15 V, 500 mW, SOD-123; Manufacturer: Diodes Inc.; SizeAreaWB_mm2: 13.095; SizeArea_mm2: 6.545; SizeY_mm: 1.7; AEC Qualified: N; SizeZ_mm: 1.35; Value1: 0.5W; SizeX_mm: 3.85; Power_W: 500mW; RJA_CperW: 425; AEC Category: Q101
D?#1 D?#2 = CMP-0077294-3: Diode, Schottky, 60 V, 15 A, TH; Manufacturer: STMicroelectronics; AEC Category: Q101; AEC Qualified: N; TJmax_C: 175°C; RJC_CperW: 0.8; SizeArea_mm2: 154.8892; Vr_V: 60V; SizeAreaWB_mm2: 209.6992; SizeX_mm: 15.245; Vf_V: 535mV; SizeY_mm: 10.16; Value1: 15A; Value2: 0.535V; SizeZ_mm: 4.445; Value: 60V
HG1 ISNS2 LG1 SW1 TP21 = CMP-0055149-2: Test Point, Multipurpose, White, TH; Manufacturer: Keystone Electronics; CNHeader: FALSE; Green_Lifecycle: Active; Green_REACh: Passed; ContactFinish: Silver; CT: TRUE
J?#1-J?#3 = CMP-0074939-1: Terminal Block, 5.08 mm, 4x1, Brass, TH; Manufacturer: On-Shore Technology; Cert_VDE: Y; CNHeader: False; Current_A: 15A; Green_Lifecycle: Not Set; Shrouded: N; Gender: Female; Green_REACh: Incomplete; Voltage_V: 300V; Row_Count: 1; Pitch_mm: 5.08; CT: True
Q21 Q23 = CMP-0001135-4: MOSFET, N-CH, 600 V, 20 A, DDPAK; Alternate Manufacturer: None; Manufacturer: AOS; SizeZ_mm: 4.445; ChType: N; Value2: 19.8 nC; VdsMax_V: 600V; SizeX_mm: 15.245; SizeAreaWB_mm2: 209.6992; SizeY_mm: 10.16; Vgs_V: 30V; QgTyp_nC: 19.8; Value: 600V; SizeArea_mm2: 154.8892; AEC Category: Q101; IdsMax_A: 20A; ChMode: Enhancement
Q?#1 Q?#2 = CMP-0000915-2: MOSFET, N-CH, 80 V, 100 A, DNK0008A (VSON-CLIP-8); Alternate Manufacturer: None; Manufacturer: Texas Instruments; SizeZ_mm: 1; ChType: N; Value2: 48 nC; VdsMax_V: 80V; SizeX_mm: 6; SizeY_mm: 5; Vgs_V: 20V; Value: 80V; SizeArea_mm2: 30; AEC Category: Q101; IdsMax_A: 100A; SizeAreaWB_mm2: 56; U/M: EA; QgTyp_nC: 48
Q?#3 = CMP-0000353-2: Transistor, PNP, 40 V, 3 A, SOT-23; Manufacturer: Diodes Inc.; TaMax_C: 150°C; Value2: 900; Value1: 3 A; Vcesat1_V: 1.7dV; SizeX_mm: 2.5; SizeY_mm: 3; TaMin_C: -55°C; IcRated_A: 3A; CompType: BJT; SizeZ_mm: 1.1; AEC Qualified: N; Value: 40 V; SizeArea_mm2: 7.5; NPN: 0; Vceo_V: 40V; PNP: 1; AEC Category: Q101; SizeAreaWB_mm2: 14; U/M: EA
R74 R79 = CMP-0023107-5: RES, 42.2, 1%, 0.1 W, 0603; Manufacturer: Yageo; Power_W: 100mW; TempCo: 100 ppm/C; Value_Code: 42R2; Value: 42.2; EIA_Code: E96; SizeX_mm: 1.6; SizeY_mm: 0.8; SizeZ_mm: 1; Value2: 0.1W; SizeArea_mm2: 1.28; CompType: Resistor; AEC Qualified: N; VDC_V: 75V; AEC Category: Q200; SizeAreaWB_mm2: 4.68
R76 R81 = CMP-0022900-4: RES, 1.00, 1%, 0.1 W, 0603; Manufacturer: Yageo; Power_W: 100mW; TempCo: 200 ppm/C; Value_Code: 1R00; Value: 1.00; EIA_Code: E96; Res_ohm: 1; SizeX_mm: 1.6; SizeY_mm: 0.8; Value2: 0.1W; SizeArea_mm2: 1.28; CompType: Resistor; AEC Qualified: N; VDC_V: 75V; AEC Category: Q200; SizeAreaWB_mm2: 4.68
R77 R82 = CMP-0023167-5: RES, 51.0 k, 1%, 0.1 W, 0603; Manufacturer: Yageo; Power_W: 100mW; TempCo: 100 ppm/C; Value_Code: 51k0; Value: 51.0k; Res_ohm: 51k; SizeX_mm: 1.6; SizeY_mm: 0.8; SizeZ_mm: 1; Value2: 0.1W; SizeArea_mm2: 1.28; AEC Qualified: N; VDC_V: 75V; AEC Category: Q200; SizeAreaWB_mm2: 4.68
R78 = CMP-0018748-3: RES, 0, 5%, 0.25 W, AEC-Q200 Grade 0, 1206; Manufacturer: Panasonic; Power_W: 250mW; TempCo: 600 ppm/C; Value_Code: 0000; Value: 0; EIA_Code: E24; SizeX_mm: 3.2; SizeY_mm: 1.6; SizeZ_mm: 1.35; Value2: 0.25W; SizeArea_mm2: 5.12; AEC Qualified: Y; VDC_V: 200V; AEC Category: Q200; SizeAreaWB_mm2: 10.92
R83 = CMP-0017949-2: RES, 187, 1%, 0.25 W, 1206; Manufacturer: Yageo America; Power_W: 250mW; TempCo: 100 ppm/C; Value_Code: 187R; U/M: EA; Value: 187; EIA_Code: E96; SizeX_mm: 3.2; SizeY_mm: 1.6; SizeZ_mm: 1.35; Value2: 0.25W; SizeArea_mm2: 5.12; VDC_V: 200V; AEC Category: Q200
R84 = CMP-0022871-5: RES, 1.21 k, 1%, 0.1 W, 0603; Manufacturer: Yageo; Power_W: 100mW; TempCo: 100 ppm/C; Value_Code: 1k21; Value: 1.21k; EIA_Code: E96; SizeX_mm: 1.6; SizeY_mm: 0.8; SizeZ_mm: 1; Value2: 0.1W; SizeArea_mm2: 1.28; AEC Qualified: N; VDC_V: 75V; AEC Category: Q200; SizeAreaWB_mm2: 4.68
R85 = CMP-0027004-2: RES, 0, 5%, 0.063 W, 0402; Manufacturer: Yageo America; Power_W: 63mW; TempCo: 200 ppm/C; Value_Code: 0000; U/M: EA; Value: 0; EIA_Code: E24; SizeX_mm: 1; SizeY_mm: 0.5; SizeZ_mm: 0.6; Value2: 0.063W; CompType: Resistor; VDC_V: 50V; AEC Category: Q200
R86 = CMP-0023332-5: RES, 9.09 k, 1%, 0.1 W, 0603; Manufacturer: Yageo; Power_W: 100mW; TempCo: 100 ppm/C; Value_Code: 9k09; Value: 9.09k; EIA_Code: E96; SizeX_mm: 1.6; SizeY_mm: 0.8; SizeZ_mm: 1; Value2: 0.1W; SizeArea_mm2: 1.28; AEC Qualified: N; VDC_V: 75V; AEC Category: Q200; SizeAreaWB_mm2: 4.68
R87 = CMP-0022981-5: RES, 2.05 k, 1%, 0.1 W, 0603; Manufacturer: Yageo; Power_W: 100mW; TempCo: 100 ppm/C; Value_Code: 2k05; Value: 2.05k; EIA_Code: E96; SizeX_mm: 1.6; SizeY_mm: 0.8; SizeZ_mm: 1; Value2: 0.1W; SizeArea_mm2: 1.28; AEC Qualified: N; VDC_V: 75V; AEC Category: Q200; SizeAreaWB_mm2: 4.68
R88 = CMP-0022800-4: RES, 147 k, 1%, 0.1 W, 0603; Manufacturer: Yageo; Power_W: 100mW; TempCo: 100 ppm/C; Value: 147k; EIA_Code: E96; SizeX_mm: 1.6; SizeY_mm: 0.8; SizeZ_mm: 1; Value2: 0.1W; SizeArea_mm2: 1.28; AEC Qualified: N; VDC_V: 75V; AEC Category: Q200; SizeAreaWB_mm2: 4.68
R89 = CMP-0022711-2: RES, 2.20, 1%, 0.1 W, 0603; Manufacturer: Panasonic; Power_W: 100mW; TempCo: 200 ppm/C; Value_Code: 2R20; U/M: EA; Value: 2.20; Res_ohm: 2.2; SizeX_mm: 1.6; SizeY_mm: 0.8; SizeZ_mm: 1; Value2: 0.1W; SizeArea_mm2: 1.28; CompType: Resistor; AEC Category: Q200
R90 = CMP-0022684-3: RES, 10.0 k, 1%, 0.1 W, 0603; Manufacturer: Panasonic; Power_W: 100mW; TempCo: 100 ppm/C; Value_Code: 10k0; U/M: EA; Value: 10.0k; EIA_Code: E96; Res_ohm: 10k; SizeX_mm: 1.6; SizeY_mm: 0.8; SizeZ_mm: 1; Value2: 0.1W; SizeArea_mm2: 1.28; CompType: Resistor; VDC_V: 75V; AEC Category: Q200
R91 R95 R103 = CMP-0087456-2: 3.3 MOhms ±1% 0.25W, 1/4W Chip Resistor 1206 (3216 Metric) Automotive AEC-Q200, High Voltage Thick Film; Manufacturer: Rohm Semiconductor; AEC Qualified: Yes; Power_W: 250mW; SizeZ_mm: 0.65mm; AEC Grade: Grade 0; TempCo: 100ppm/°C; VDC_V: 500V
R92 = CMP-0026658-1: RES, 10.0 k, 1%, 0.1 W, 0402; Manufacturer: Panasonic; Power_W: 100mW; TempCo: 100 ppm/C; Value_Code: 10k0; U/M: EA; Value: 10.0k; EIA_Code: E96; Res_ohm: 10k; SizeX_mm: 1; SizeY_mm: 0.5; SizeZ_mm: 0.6; Value2: 0.1W; VDC_V: 50V; AEC Category: Q200
R96 = CMP-0023036-5: RES, 33.2 k, 1%, 0.1 W, 0603; Manufacturer: Yageo; Power_W: 100mW; TempCo: 100 ppm/C; Value_Code: 33k2; Value: 33.2k; EIA_Code: E96; SizeX_mm: 1.6; SizeY_mm: 0.8; SizeZ_mm: 1; Value2: 0.1W; SizeArea_mm2: 1.28; AEC Qualified: N; VDC_V: 75V; AEC Category: Q200; SizeAreaWB_mm2: 4.68
R98-R100 = CMP-0016708-3: RES, 1.65 k, 1%, 0.25 W, AEC-Q200 Grade 0, 1206; Manufacturer: Vishay-Dale; Power_W: 250mW; TempCo: 100 ppm/C; Value_Code: 1k65; Value: 1.65k; EIA_Code: E96; SizeX_mm: 3.2; SizeY_mm: 1.6; SizeZ_mm: 1.35; Value2: 0.25W; SizeArea_mm2: 5.12; CompType: Resistor; AEC Qualified: Y; VDC_V: 200V; AEC Category: Q200; AEC Grade: 0
R102 R105 = CMP-0023780-3: RES, 15.0 k, 0.1%, 0.1 W, 0603; Manufacturer: Yageo America; Power_W: 100mW; TempCo: 25 ppm/C; Value_Code: 15k0; U/M: EA; Value: 15.0k; EIA_Code: E192; Res_ohm: 15k; SizeX_mm: 1.6; SizeY_mm: 0.8; SizeZ_mm: 1; Value2: 0.1W; SizeArea_mm2: 1.28; VDC_V: 75V; AEC Category: Q200
R106 = CMP-0022830-5: RES, 16.9 k, 1%, 0.1 W, 0603; Manufacturer: Yageo; Power_W: 100mW; TempCo: 100 ppm/C; Value_Code: 16k9; Value: 16.9k; EIA_Code: E96; SizeX_mm: 1.6; SizeY_mm: 0.8; SizeZ_mm: 1; Value2: 0.1W; SizeArea_mm2: 1.28; AEC Qualified: N; VDC_V: 75V; AEC Category: Q200; SizeAreaWB_mm2: 4.68
R108 R111 = CMP-0023441-3: RES, 15.0 k, 0.1%, 0.1 W, 0603; Manufacturer: Susumu Co Ltd; Power_W: 100mW; TempCo: 25 ppm/C; Value_Code: 15k0; U/M: EA; Value: 15.0k; EIA_Code: E192; Res_ohm: 15k; SizeX_mm: 1.6; SizeY_mm: 0.8; SizeZ_mm: 1; Value2: 0.1W; SizeArea_mm2: 1.28; VDC_V: 75V; AEC Category: Q200
R109 = CMP-0096703-1: NTC Thermistor 470k 0603 (1608 Metric); Manufacturer: TDK; AEC Qualified: No; Res_ohm: 470kΩ; Power_W: 180mW; B 25 50: 4386K; B 25 100: 4480K; SizeZ_mm: 0.9mm; B 25 85: 4455K; B Tolerance: 3%; Tolerance_%: 5%
R110 R112 = CMP-0023630-3: RES, 100 k, 0.1%, 0.1 W, 0603; Manufacturer: Yageo America; Power_W: 100mW; TempCo: 25 ppm/C; U/M: EA; Value: 100k; EIA_Code: E192; SizeX_mm: 1.6; SizeY_mm: 0.8; SizeZ_mm: 1; Value2: 0.1W; SizeArea_mm2: 1.28; VDC_V: 75V; AEC Category: Q200
R?#1 = CMP-0093609-1: 0Ω ±0 0.25W 1206 Thick Film Chip Resistor AEC-Q200 compliant; Manufacturer: Stackpole Electronics; AEC Qualified: Yes; VDC_V: 200V; AEC Grade: Grade 0; Power_W: 250mW; SizeZ_mm: 0.7mm
R?#2 R?#3 R?#5 = CMP-0023000-5: RES, 2.00 k, 1%, 0.1 W, 0603; Manufacturer: Yageo; Power_W: 100mW; TempCo: 100 ppm/C; Value_Code: 2k00; Value: 2.00k; EIA_Code: E96; Res_ohm: 2k; SizeX_mm: 1.6; SizeY_mm: 0.8; SizeZ_mm: 1; Value2: 0.1W; SizeArea_mm2: 1.28; AEC Qualified: N; VDC_V: 75V; AEC Category: Q200; SizeAreaWB_mm2: 4.68
R?#4 R?#6 = CMP-0025885-5: RES, 0, 5%, 0.1 W, 0603; Manufacturer: Yageo; Power_W: 100mW; TempCo: 200 ppm/C; Value_Code: 0000; Value: 0; EIA_Code: E24; SizeX_mm: 1.6; SizeZ_mm: 1; Value2: 0.1W; SizeArea_mm2: 1.28; AEC Qualified: N; VDC_V: 75V; AEC Category: Q200; SizeY_mm: 0.8; SizeAreaWB_mm2: 4.68
R?#7 = CMP-0022919-4: RES, 221 k, 1%, 0.1 W, 0603; Manufacturer: Yageo; Power_W: 100mW; TempCo: 100 ppm/C; Value: 221k; EIA_Code: E96; SizeX_mm: 1.6; SizeY_mm: 0.8; SizeZ_mm: 1; Value2: 0.1W; SizeArea_mm2: 1.28; AEC Qualified: N; VDC_V: 75V; AEC Category: Q200; SizeAreaWB_mm2: 4.68
T9 = CMP-0120309-1: Transformer; Manufacturer: Payton Planar; Ind_H: 250µH; Ns1toNp: 15:2; SizeZ_mm: 10mm; AEC Qualified: No; Frequency_Fixed: 70-160kHz; TaMax_C: +30°C; TaMin_C: -40°C; Voltage_Isolation_Vrms: 2500VDC
TP14 TP19 Vin2 = CMP-0055147-2: Test Point, Multipurpose, Red, TH; Manufacturer: Keystone Electronics; CNHeader: FALSE; Green_Lifecycle: Active; Green_REACh: Passed; ContactFinish: Silver; CT: TRUE
TP15 TP16 = CMP-0055148-2: Test Point, Multipurpose, Black, TH; Manufacturer: Keystone Electronics; CNHeader: FALSE; ContactFinish: Silver; Green_REACh: Passed; Green_Lifecycle: Active; CT: TRUE
TP17 TP18 = CMP-0055148-2: Test Point, Multipurpose, Black, TH; Manufacturer: Keystone Electronics; CNHeader: FALSE; Green_Lifecycle: Active; Green_REACh: Passed; ContactFinish: Silver; CT: TRUE
TP20 = CMP-0055150-2: Test Point, Multipurpose, Orange, TH; Manufacturer: Keystone Electronics; CNHeader: FALSE; Green_Lifecycle: Active; Green_REACh: Passed; ContactFinish: Silver; CT: TRUE
U9 = CMP-0083653-1: Optocoupler, 5.3 kV, 100-200% CTR, SMT; Manufacturer: Vishay-Semiconductor; CTR (Max): 200%; SizeAreaWB_mm2: 71.064; CTR (Min): 100%; SizeZ_mm: 5; SizeX_mm: 8.8; SizeY_mm: 4.58; SizeArea_mm2: 40.304; Voltage_Isolation_Vrms: 5.3kV
U11 = CMP-0095299-1: 750kHz Wide VIN/VOUT Range LLC Controller Optimized for Light Load Efficiency; Manufacturer: Texas Instruments; Number Of Outputs: 2; TaMax_C: +125°C; Output Type: Other; TJmax_C: +150°C; AEC Qualified: No; Standoff Height: 0.1mm; TaMin_C: -40°C; SizeZ_mm: 1.75mm; Switching Frequency: 30-750kHz; Max Supply Voltage: 18.5V
U12 = CMP-0033066-1: Low-Voltage Adjustable Precision Shunt Regulator, 129 ppm / degC, 80 mA, 0 to 70 degC, 3-pin SOT-23 (DBZ), Green (RoHS & no Sb/Br); Manufacturer: Texas Instruments; Min Iz for Regulation(uA): 80; VO Adj(Max)(V): 18; VO Adj(Min)(V): 1.24; Rating: Catalog; SubFamily: Shunt Voltage Reference; Temp Coeff(Max)(ppm/ degree C): 129
U?#1 U?#2 = CMP-0013047-3: High-Frequency Multi-Mode Synchronous Rectifier Controller, DBV0005A (SOT-23-5); Manufacturer: Texas Instruments; Alternate PartNumber: UCC24612-2DBVR; SizeX_mm: 2.8; SizeY_mm: 2.9; CompType: IC; SizeZ_mm: 1.45; SizeArea_mm2: 8.12; SizeAreaWB_mm2: 14.82; AEC Category: Q200; AEC Qualified: N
